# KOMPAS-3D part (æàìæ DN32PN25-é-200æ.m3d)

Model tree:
1. Объединить компоненты:1  (labels: СЕНС DN32PN25-В-200С)

Referenced files in D:\Савин\!СЕНСОР\3D для заказчика\!Новый перечень\СЕНС\4. СЕНС-В-200С\DN32\: СЕНС DN32PN25-В-200С.a3d
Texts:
  СЕНС DN32PN25-В-200С
  ООО НПП Сенсор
